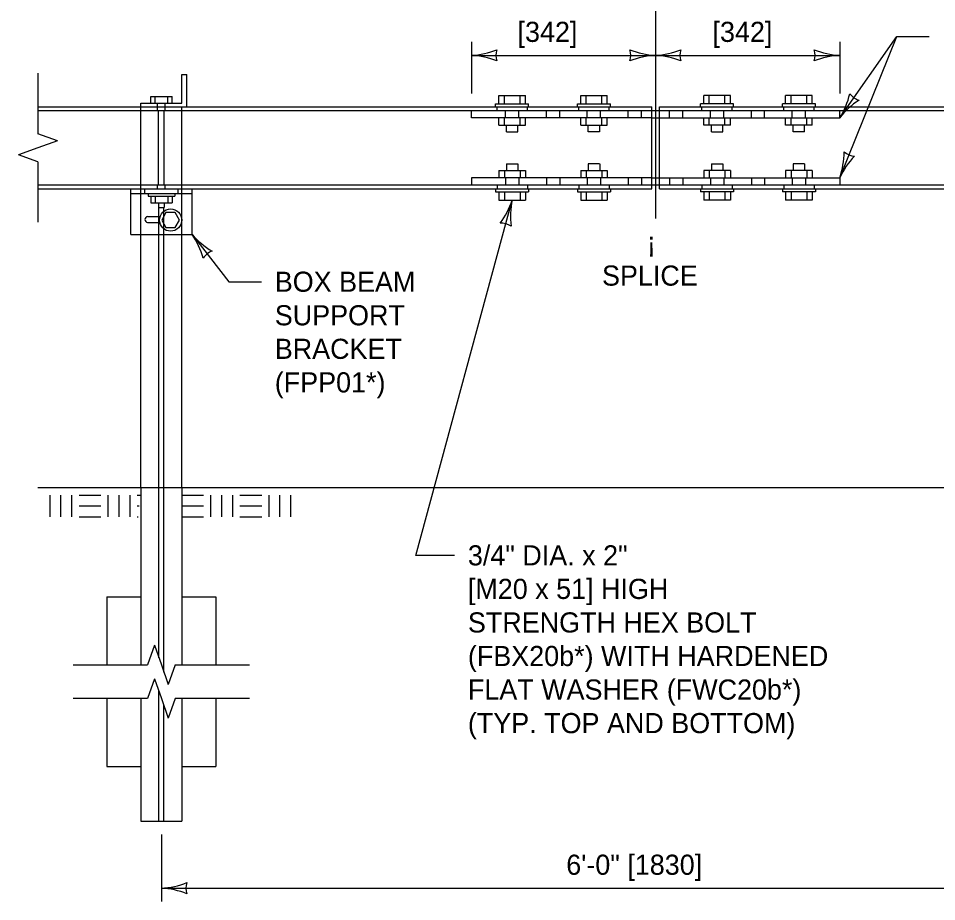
# Model space of a CAD drawing. Extents: x 49991.4 to 50021, y 49987.6 to 50011.4.
# Drawn here: x 50015.21 to 50017.948, y 50004.162 to 50006.795 of the extents above; entities that cross this region are included whole.
import ezdxf

# ---------------------------------------------------------------- set-up
doc = ezdxf.new("R2010")
doc.units = 0
for name, color, linetype in [('Level 1', 7, 'Continuous'), ('Level 2', 7, 'Continuous'), ('Level 3', 7, 'Continuous'), ('Level 4', 7, 'Continuous'), ('Level 5', 7, 'Continuous'), ('Level 6', 7, 'Continuous')]:
    doc.layers.add(name, color=color, linetype=linetype)

msp = doc.modelspace()

# ---------------------------------------------------------------- linework, layer by layer
at = {"layer": 'Level 1'}
for p, q in [((50015.6973, 50006.5419), (50015.6973, 50006.627)), ((50015.6973, 50006.627), (50015.7125, 50006.627)), ((50015.7125, 50006.5309), (50015.7125, 50006.627)), ((50016.6429, 50006.5401), (50016.6429, 50006.5645)), ((50016.6429, 50006.5645), (50016.7218, 50006.5645)), ((50016.659, 50006.5401), (50016.659, 50006.5645)), ((50016.7057, 50006.5401), (50016.7057, 50006.5645)), ((50016.7218, 50006.5401), (50016.7218, 50006.5645)), ((50016.8866, 50006.5401), (50016.8866, 50006.5645)), ((50016.8866, 50006.5645), (50016.9654, 50006.5645)), ((50016.9026, 50006.5401), (50016.9026, 50006.5645)), ((50016.9494, 50006.5401), (50016.9494, 50006.5645)), ((50016.9654, 50006.5401), (50016.9654, 50006.5645)), ((50017.2538, 50006.5401), (50017.2538, 50006.5645)), ((50017.3326, 50006.5645), (50017.2538, 50006.5645)), ((50017.2698, 50006.5401), (50017.2698, 50006.5645)), ((50017.3166, 50006.5401), (50017.3166, 50006.5645)), ((50017.3326, 50006.5401), (50017.3326, 50006.5645)), ((50017.4974, 50006.5401), (50017.4974, 50006.5645)), ((50017.5763, 50006.5645), (50017.4974, 50006.5645)), ((50017.5135, 50006.5401), (50017.5135, 50006.5645)), ((50017.5602, 50006.5401), (50017.5602, 50006.5645)), ((50017.5763, 50006.5401), (50017.5763, 50006.5645)), ((50015.5754, 50006.5309), (50015.5754, 50006.5419)), ((50015.5754, 50006.5419), (50015.6973, 50006.5419)), ((50015.6048, 50006.5419), (50015.6048, 50006.5616)), ((50015.6048, 50006.5616), (50015.6687, 50006.5616)), ((50015.6178, 50006.5419), (50015.6178, 50006.5616)), ((50015.6556, 50006.5419), (50015.6556, 50006.5616)), ((50015.6687, 50006.5419), (50015.6687, 50006.5616)), ((50016.6328, 50006.5401), (50016.7312, 50006.5401)), ((50016.6328, 50006.5309), (50016.6328, 50006.5401)), ((50016.7312, 50006.5309), (50016.7312, 50006.5401)), ((50016.8772, 50006.5401), (50016.9755, 50006.5401)), ((50016.8772, 50006.5309), (50016.8772, 50006.5401)), ((50016.9755, 50006.5309), (50016.9755, 50006.5401)), ((50017.342, 50006.5401), (50017.2437, 50006.5401)), ((50017.2437, 50006.5309), (50017.2437, 50006.5401)), ((50017.342, 50006.5309), (50017.342, 50006.5401)), ((50017.5864, 50006.5401), (50017.488, 50006.5401)), ((50017.488, 50006.5309), (50017.488, 50006.5401)), ((50017.5864, 50006.5309), (50017.5864, 50006.5401)), ((50015.2686, 50006.5309), (50017.0982, 50006.5309)), ((50017.0982, 50006.287), (50017.0982, 50006.5309)), ((50017.0982, 50006.5198), (50017.121, 50006.5198)), ((50017.121, 50006.5309), (50019.3683, 50006.5309)), ((50017.121, 50006.287), (50017.121, 50006.5309)), ((50017.0982, 50006.4982), (50017.121, 50006.4982)), ((50017.0982, 50006.3197), (50017.121, 50006.3197)), ((50017.0982, 50006.2981), (50017.121, 50006.2981)), ((50015.2686, 50006.287), (50017.0982, 50006.287)), ((50015.545, 50006.1508), (50015.545, 50006.287)), ((50015.545, 50006.2724), (50015.7278, 50006.2724)), ((50015.5966, 50006.2724), (50015.5966, 50006.2649)), ((50015.5966, 50006.2649), (50015.6763, 50006.2649)), ((50015.6048, 50006.2649), (50015.6048, 50006.2452)), ((50015.6178, 50006.2649), (50015.6178, 50006.2452)), ((50015.6556, 50006.2649), (50015.6556, 50006.2452)), ((50015.6687, 50006.2649), (50015.6687, 50006.2452)), ((50015.6763, 50006.2724), (50015.6763, 50006.2649)), ((50015.7278, 50006.1508), (50015.7278, 50006.287)), ((50016.6328, 50006.287), (50016.6328, 50006.2777)), ((50016.6328, 50006.2777), (50016.7312, 50006.2777)), ((50016.6429, 50006.2777), (50016.6429, 50006.2533)), ((50016.659, 50006.2777), (50016.659, 50006.2533)), ((50016.7057, 50006.2777), (50016.7057, 50006.2533)), ((50016.7218, 50006.2777), (50016.7218, 50006.2533)), ((50016.7312, 50006.287), (50016.7312, 50006.2777)), ((50016.8772, 50006.287), (50016.8772, 50006.2777)), ((50016.8772, 50006.2777), (50016.9755, 50006.2777)), ((50016.8866, 50006.2777), (50016.8866, 50006.2533)), ((50016.9026, 50006.2777), (50016.9026, 50006.2533)), ((50016.9494, 50006.2777), (50016.9494, 50006.2533)), ((50016.9654, 50006.2777), (50016.9654, 50006.2533)), ((50016.9755, 50006.287), (50016.9755, 50006.2777)), ((50017.121, 50006.287), (50019.3683, 50006.287)), ((50017.2437, 50006.287), (50017.2437, 50006.2777)), ((50017.342, 50006.2777), (50017.2437, 50006.2777)), ((50017.2538, 50006.2777), (50017.2538, 50006.2533)), ((50017.2698, 50006.2777), (50017.2698, 50006.2533)), ((50017.3166, 50006.2777), (50017.3166, 50006.2533)), ((50017.3326, 50006.2777), (50017.3326, 50006.2533)), ((50017.342, 50006.287), (50017.342, 50006.2777)), ((50017.488, 50006.287), (50017.488, 50006.2777)), ((50017.5864, 50006.2777), (50017.488, 50006.2777)), ((50017.4974, 50006.2777), (50017.4974, 50006.2533)), ((50017.5135, 50006.2777), (50017.5135, 50006.2533)), ((50017.5602, 50006.2777), (50017.5602, 50006.2533)), ((50017.5763, 50006.2777), (50017.5763, 50006.2533)), ((50017.5864, 50006.287), (50017.5864, 50006.2777)), ((50015.6048, 50006.2452), (50015.6687, 50006.2452)), ((50016.6429, 50006.2533), (50016.7218, 50006.2533)), ((50016.8866, 50006.2533), (50016.9654, 50006.2533)), ((50017.3326, 50006.2533), (50017.2538, 50006.2533)), ((50017.5763, 50006.2533), (50017.4974, 50006.2533)), ((50015.5954, 50006.2045), (50015.6326, 50006.2045)), ((50015.5954, 50006.1859), (50015.6316, 50006.1859)), ((50015.545, 50006.1508), (50015.7278, 50006.1508)), ((50015.5754, 50005.3957), (50015.5754, 50006.1508)), ((50015.6973, 50005.3957), (50015.6973, 50006.1508)), ((50019.3683, 50005.3957), (50015.2686, 50005.3957)), ((50015.3046, 50005.3091), (50015.3046, 50005.3741)), ((50015.3371, 50005.3091), (50015.3371, 50005.3741)), ((50015.3696, 50005.3091), (50015.3696, 50005.3741)), ((50015.3913, 50005.3741), (50015.4563, 50005.3741)), ((50015.478, 50005.3091), (50015.478, 50005.3741)), ((50015.5105, 50005.3091), (50015.5105, 50005.3741)), ((50015.543, 50005.3091), (50015.543, 50005.3741)), ((50015.6974, 50005.3741), (50015.6974, 50005.3741)), ((50015.6974, 50005.3741), (50015.7623, 50005.3741)), ((50015.7841, 50005.3091), (50015.7841, 50005.3741)), ((50015.8166, 50005.3091), (50015.8166, 50005.3741)), ((50015.849, 50005.3091), (50015.849, 50005.3741)), ((50015.8707, 50005.3741), (50015.9357, 50005.3741)), ((50015.9574, 50005.3091), (50015.9574, 50005.3741)), ((50015.9899, 50005.3091), (50015.9899, 50005.3741)), ((50016.0224, 50005.3091), (50016.0224, 50005.3741)), ((50015.3913, 50005.3416), (50015.4563, 50005.3416)), ((50015.6974, 50005.3416), (50015.7623, 50005.3416)), ((50015.8707, 50005.3416), (50015.9357, 50005.3416)), ((50015.3913, 50005.3091), (50015.4563, 50005.3091)), ((50015.6974, 50005.3091), (50015.7623, 50005.3091)), ((50015.8707, 50005.3091), (50015.9357, 50005.3091))]:
    msp.add_line(p, q, dxfattribs=at)
for points in [[(50015.6279, 50006.2452), (50015.6279, 50006.231)], [(50015.6449, 50006.2452), (50015.6449, 50006.231)], [(50015.6279, 50006.231), (50015.6449, 50006.231)], [(50015.5754, 50005.3957), (50015.5754, 50005.3957)], [(50015.6974, 50005.3957), (50015.6974, 50005.3957)], [(50015.5646, 50005.3741), (50015.5735, 50005.3741)], [(50015.5646, 50005.3416), (50015.5705, 50005.3416)], [(50015.5646, 50005.3091), (50015.5674, 50005.3091)]]:
    msp.add_lwpolyline(points, dxfattribs=at)
msp.add_lwpolyline([(50015.6499, 50006.1713), (50015.678, 50006.1713), (50015.6903, 50006.1936), (50015.678, 50006.2161), (50015.6499, 50006.2161), (50015.6376, 50006.1936)], close=True, dxfattribs=at)
msp.add_circle((50015.664, 50006.1936), 0.0333, dxfattribs=at)
msp.add_arc((50015.5968, 50006.1952), 0.00938, 98.5498, 261.4502, dxfattribs=at)
at = {"layer": 'Level 3'}
for p, q in [((50016.395, 50005.1943), (50016.6823, 50006.2533)), ((50016.5102, 50005.1943), (50016.395, 50005.1943))]:
    msp.add_line(p, q, dxfattribs=at)
for points in [[(50017.6587, 50006.4982), (50017.8285, 50006.7405)], [(50017.6587, 50006.3197), (50017.8285, 50006.7405)], [(50017.8285, 50006.7405), (50017.9257, 50006.7405)], [(50016.5605, 50006.7245), (50016.5605, 50006.5709)], [(50017.6587, 50006.7245), (50017.6587, 50006.5709)], [(50016.5605, 50006.6845), (50017.1096, 50006.6845)], [(50017.1096, 50006.6845), (50017.6587, 50006.6845)], [(50015.7278, 50006.1508), (50015.8373, 50006.0098)], [(50015.8373, 50006.0098), (50015.9345, 50006.0098)], [(50015.6364, 50004.3622), (50015.6364, 50004.1622)], [(50015.6364, 50004.2022), (50018.5614, 50004.2022)]]:
    msp.add_lwpolyline(points, dxfattribs=at)
for centre, radius, start, end in [((50016.549, 50006.9172), 0.233, 272.8273, 292.0772), ((50016.6887, 50006.6845), 0.0548, 162.1388, 197.8612), ((50017.1182, 50006.9066), 0.2223, 247.456, 267.6395), ((50016.9808, 50006.6845), 0.0548, 342.1388, 17.8612), ((50017.0975, 50006.9172), 0.233, 272.8273, 292.0772), ((50017.2372, 50006.6845), 0.0548, 162.1388, 197.8612), ((50017.6678, 50006.9066), 0.2223, 247.456, 267.6395), ((50017.5305, 50006.6845), 0.0548, 342.1388, 17.8612), ((50016.5513, 50006.4624), 0.2223, 67.456, 87.6395), ((50017.1205, 50006.4518), 0.233, 92.8273, 112.0772), ((50017.0998, 50006.4624), 0.2223, 67.456, 87.6395), ((50017.6702, 50006.4518), 0.233, 92.8273, 112.0772), ((50017.4615, 50006.6223), 0.233, 327.8051, 347.055), ((50017.7323, 50006.6032), 0.0548, 217.1167, 252.839), ((50017.8354, 50006.3632), 0.2223, 122.4338, 142.6174), ((50017.4386, 50006.3961), 0.233, 340.8524, 0.1022), ((50017.8613, 50006.2281), 0.2223, 135.4811, 155.6646), ((50017.7067, 50006.4386), 0.0548, 230.1639, 265.8863), ((50016.4704, 50006.3203), 0.2223, 322.2773, 342.4608), ((50016.91, 50006.2035), 0.233, 167.6486, 186.8984), ((50016.6488, 50006.1296), 0.0548, 56.9601, 92.6824), ((50015.5467, 50006.0218), 0.2223, 15.2888, 35.4723), ((50015.9045, 50006.3026), 0.233, 220.6601, 239.9099), ((50015.8064, 50006.0495), 0.0548, 109.9716, 145.6939), ((50015.6249, 50004.4349), 0.233, 272.8273, 292.0772), ((50015.7646, 50004.2022), 0.0548, 162.1388, 197.8612), ((50015.6272, 50003.9801), 0.2223, 67.456, 87.6395)]:
    msp.add_arc(centre, radius, start, end, dxfattribs=at)
at = {"layer": 'Level 4'}
for p, q in [((50015.625, 50006.5198), (50015.625, 50006.5419)), ((50015.6477, 50006.5198), (50015.6477, 50006.5419)), ((50015.2686, 50006.5198), (50017.0982, 50006.5198)), ((50015.5754, 50006.1508), (50015.5754, 50006.5309)), ((50015.6279, 50006.2981), (50015.6279, 50006.5198)), ((50015.6449, 50006.2981), (50015.6449, 50006.5198)), ((50015.6973, 50006.1508), (50015.6973, 50006.5309)), ((50016.5605, 50006.4982), (50016.5605, 50006.5198)), ((50016.6626, 50006.4982), (50016.6626, 50006.5198)), ((50016.7022, 50006.4982), (50016.7022, 50006.5198)), ((50016.7844, 50006.4982), (50016.7844, 50006.5198)), ((50016.824, 50006.4982), (50016.824, 50006.5198)), ((50016.9062, 50006.4982), (50016.9062, 50006.5198)), ((50016.9458, 50006.4982), (50016.9458, 50006.5198)), ((50017.028, 50006.4982), (50017.028, 50006.5198)), ((50017.0676, 50006.4982), (50017.0676, 50006.5198)), ((50017.121, 50006.5198), (50019.3683, 50006.5198)), ((50017.1516, 50006.4982), (50017.1516, 50006.5198)), ((50017.1912, 50006.4982), (50017.1912, 50006.5198)), ((50017.2734, 50006.4982), (50017.2734, 50006.5198)), ((50017.313, 50006.4982), (50017.313, 50006.5198)), ((50017.3952, 50006.4982), (50017.3952, 50006.5198)), ((50017.4348, 50006.4982), (50017.4348, 50006.5198)), ((50017.517, 50006.4982), (50017.517, 50006.5198)), ((50017.5566, 50006.4982), (50017.5566, 50006.5198)), ((50017.6587, 50006.4982), (50017.6587, 50006.5198)), ((50017.0982, 50006.4982), (50016.5605, 50006.4982)), ((50016.6429, 50006.4768), (50016.6429, 50006.4982)), ((50016.659, 50006.4768), (50016.659, 50006.4982)), ((50016.7057, 50006.4768), (50016.7057, 50006.4982)), ((50016.7218, 50006.4768), (50016.7218, 50006.4982)), ((50016.8866, 50006.4768), (50016.8866, 50006.4982)), ((50016.9026, 50006.4768), (50016.9026, 50006.4982)), ((50016.9494, 50006.4768), (50016.9494, 50006.4982)), ((50016.9654, 50006.4768), (50016.9654, 50006.4982)), ((50017.121, 50006.4982), (50017.6587, 50006.4982)), ((50017.2538, 50006.4768), (50017.2538, 50006.4982)), ((50017.2698, 50006.4768), (50017.2698, 50006.4982)), ((50017.3166, 50006.4768), (50017.3166, 50006.4982)), ((50017.3326, 50006.4768), (50017.3326, 50006.4982)), ((50017.4974, 50006.4768), (50017.4974, 50006.4982)), ((50017.5135, 50006.4768), (50017.5135, 50006.4982)), ((50017.5602, 50006.4768), (50017.5602, 50006.4982)), ((50017.5763, 50006.4768), (50017.5763, 50006.4982)), ((50016.6429, 50006.4768), (50016.7218, 50006.4768)), ((50016.6654, 50006.4567), (50016.6654, 50006.4768)), ((50016.6654, 50006.4567), (50016.6994, 50006.4567)), ((50016.6994, 50006.4567), (50016.6994, 50006.4768)), ((50016.8866, 50006.4768), (50016.9654, 50006.4768)), ((50016.909, 50006.4567), (50016.909, 50006.4768)), ((50016.9429, 50006.4567), (50016.909, 50006.4567)), ((50016.943, 50006.4567), (50016.943, 50006.4768)), ((50017.3326, 50006.4768), (50017.2538, 50006.4768)), ((50017.2762, 50006.4567), (50017.2762, 50006.4768)), ((50017.2763, 50006.4567), (50017.3102, 50006.4567)), ((50017.3102, 50006.4567), (50017.3102, 50006.4768)), ((50017.5763, 50006.4768), (50017.4974, 50006.4768)), ((50017.5198, 50006.4567), (50017.5198, 50006.4768)), ((50017.5538, 50006.4567), (50017.5198, 50006.4567)), ((50017.5538, 50006.4567), (50017.5538, 50006.4768)), ((50016.6654, 50006.3612), (50016.6654, 50006.3411)), ((50016.6654, 50006.3612), (50016.6994, 50006.3612)), ((50016.6994, 50006.3612), (50016.6994, 50006.3411)), ((50016.909, 50006.3612), (50016.909, 50006.3411)), ((50016.9429, 50006.3612), (50016.909, 50006.3612)), ((50016.943, 50006.3612), (50016.943, 50006.3411)), ((50017.2762, 50006.3612), (50017.2762, 50006.3411)), ((50017.2763, 50006.3612), (50017.3102, 50006.3612)), ((50017.3102, 50006.3612), (50017.3102, 50006.3411)), ((50017.5198, 50006.3612), (50017.5198, 50006.3411)), ((50017.5538, 50006.3612), (50017.5198, 50006.3612)), ((50017.5538, 50006.3612), (50017.5538, 50006.3411)), ((50017.0982, 50006.3197), (50016.5605, 50006.3197)), ((50016.5605, 50006.3197), (50016.5605, 50006.2981)), ((50016.6429, 50006.3411), (50016.6429, 50006.3197)), ((50016.6429, 50006.3411), (50016.7218, 50006.3411)), ((50016.659, 50006.3411), (50016.659, 50006.3197)), ((50016.6626, 50006.3197), (50016.6626, 50006.2981)), ((50016.7022, 50006.3197), (50016.7022, 50006.2981)), ((50016.7057, 50006.3411), (50016.7057, 50006.3197)), ((50016.7218, 50006.3411), (50016.7218, 50006.3197)), ((50016.7844, 50006.3197), (50016.7844, 50006.2981)), ((50016.824, 50006.3197), (50016.824, 50006.2981)), ((50016.8866, 50006.3411), (50016.8866, 50006.3197)), ((50016.8866, 50006.3411), (50016.9654, 50006.3411)), ((50016.9026, 50006.3411), (50016.9026, 50006.3197)), ((50016.9062, 50006.3197), (50016.9062, 50006.2981)), ((50016.9458, 50006.3197), (50016.9458, 50006.2981)), ((50016.9494, 50006.3411), (50016.9494, 50006.3197)), ((50016.9654, 50006.3411), (50016.9654, 50006.3197)), ((50017.028, 50006.3197), (50017.028, 50006.2981)), ((50017.0676, 50006.3197), (50017.0676, 50006.2981)), ((50017.121, 50006.3197), (50017.6587, 50006.3197)), ((50017.1516, 50006.3197), (50017.1516, 50006.2981)), ((50017.1912, 50006.3197), (50017.1912, 50006.2981)), ((50017.2538, 50006.3411), (50017.2538, 50006.3197)), ((50017.3326, 50006.3411), (50017.2538, 50006.3411)), ((50017.2698, 50006.3411), (50017.2698, 50006.3197)), ((50017.2734, 50006.3197), (50017.2734, 50006.2981)), ((50017.313, 50006.3197), (50017.313, 50006.2981)), ((50017.3166, 50006.3411), (50017.3166, 50006.3197)), ((50017.3326, 50006.3411), (50017.3326, 50006.3197)), ((50017.3952, 50006.3197), (50017.3952, 50006.2981)), ((50017.4348, 50006.3197), (50017.4348, 50006.2981)), ((50017.4974, 50006.3411), (50017.4974, 50006.3197)), ((50017.5763, 50006.3411), (50017.4974, 50006.3411)), ((50017.5135, 50006.3411), (50017.5135, 50006.3197)), ((50017.517, 50006.3197), (50017.517, 50006.2981)), ((50017.5566, 50006.3197), (50017.5566, 50006.2981)), ((50017.5602, 50006.3411), (50017.5602, 50006.3197)), ((50017.5763, 50006.3411), (50017.5763, 50006.3197)), ((50017.6587, 50006.3197), (50017.6587, 50006.2981)), ((50015.2686, 50006.2981), (50017.0982, 50006.2981)), ((50015.625, 50006.287), (50015.625, 50006.2981)), ((50015.6477, 50006.287), (50015.6477, 50006.2981)), ((50017.121, 50006.2981), (50019.3683, 50006.2981)), ((50015.5874, 50006.2724), (50015.5874, 50006.287)), ((50015.6861, 50006.2724), (50015.6861, 50006.287)), ((50015.6288, 50004.889), (50015.6288, 50006.231)), ((50015.644, 50004.8461), (50015.644, 50006.231)), ((50015.5754, 50005.3957), (50015.5754, 50004.8676)), ((50015.6974, 50005.3957), (50015.6974, 50004.8676)), ((50015.4739, 50005.0708), (50015.5754, 50005.0708)), ((50015.4739, 50005.0708), (50015.4739, 50004.8676)), ((50015.6974, 50005.0708), (50015.7989, 50005.0708)), ((50015.7989, 50005.0708), (50015.7989, 50004.8676)), ((50015.6288, 50004.4022), (50015.6288, 50004.7893)), ((50015.4739, 50004.7678), (50015.4739, 50004.5647)), ((50015.5754, 50004.7678), (50015.5754, 50004.4022)), ((50015.6974, 50004.7678), (50015.6974, 50004.4022)), ((50015.7989, 50004.7678), (50015.7989, 50004.5647)), ((50015.644, 50004.4022), (50015.644, 50004.7464)), ((50015.4739, 50004.5647), (50015.5754, 50004.5647)), ((50015.6974, 50004.5647), (50015.7989, 50004.5647)), ((50015.5754, 50004.4022), (50015.6974, 50004.4022))]:
    msp.add_line(p, q, dxfattribs=at)
for points in [[(50016.6372, 50006.5198), (50016.6372, 50006.5309)], [(50016.7276, 50006.5198), (50016.7276, 50006.5309)], [(50016.8809, 50006.5198), (50016.8809, 50006.5309)], [(50016.9713, 50006.5198), (50016.9713, 50006.5309)], [(50017.2479, 50006.5198), (50017.2479, 50006.5309)], [(50017.3383, 50006.5198), (50017.3383, 50006.5309)], [(50017.4916, 50006.5198), (50017.4916, 50006.5309)], [(50017.582, 50006.5198), (50017.582, 50006.5309)], [(50016.6372, 50006.2981), (50016.6372, 50006.287)], [(50016.7276, 50006.2981), (50016.7276, 50006.287)], [(50016.8809, 50006.2981), (50016.8809, 50006.287)], [(50016.9713, 50006.2981), (50016.9713, 50006.287)], [(50017.2479, 50006.2981), (50017.2479, 50006.287)], [(50017.3383, 50006.2981), (50017.3383, 50006.287)], [(50017.4916, 50006.2981), (50017.4916, 50006.287)], [(50017.582, 50006.2981), (50017.582, 50006.287)]]:
    msp.add_lwpolyline(points, dxfattribs=at)
at = {"layer": 'Level 5'}
msp.add_lwpolyline([(50017.109, 50007.7118), (50017.109, 50006.1981)], dxfattribs=at)
at = {"layer": 'Level 6'}
for p, q in [((50015.2686, 50006.6309), (50015.2686, 50006.4501)), ((50015.327, 50006.4293), (50015.2686, 50006.4501)), ((50015.327, 50006.4293), (50015.2686, 50006.4086)), ((50015.2686, 50006.4086), (50015.2101, 50006.3879)), ((50015.2686, 50006.3672), (50015.2101, 50006.3879)), ((50015.2686, 50006.3672), (50015.2686, 50006.187)), ((50015.6157, 50004.9261), (50015.595, 50004.8676)), ((50015.6157, 50004.9261), (50015.6364, 50004.8676)), ((50015.3739, 50004.8676), (50015.595, 50004.8676)), ((50015.6364, 50004.8676), (50015.6571, 50004.8091)), ((50015.6778, 50004.8676), (50015.6571, 50004.8091)), ((50015.6778, 50004.8676), (50015.8989, 50004.8676)), ((50015.6157, 50004.8263), (50015.595, 50004.7678)), ((50015.6157, 50004.8263), (50015.6364, 50004.7678)), ((50015.595, 50004.7678), (50015.3739, 50004.7678)), ((50015.6364, 50004.7678), (50015.6571, 50004.7093)), ((50015.6778, 50004.7678), (50015.6571, 50004.7093)), ((50015.8989, 50004.7678), (50015.6778, 50004.7678))]:
    msp.add_line(p, q, dxfattribs=at)

# ---------------------------------------------------------------- texts
at = {"layer": 'Level 2'}
for s, p in [('[342]', (50016.6982, 50006.7245)), ('[342]', (50017.2794, 50006.7245)), ('¡', (50017.0839, 50006.0981)), ('SPLICE', (50016.95, 50005.9981)), ('BOX BEAM', (50015.9745, 50005.9798)), ('SUPPORT', (50015.9745, 50005.8798)), ('BRACKET', (50015.9745, 50005.7798)), ('(FPP01*)', (50015.9745, 50005.6798)), ('3/4" DIA. x 2" ', (50016.5502, 50005.1643)), ('[M20 x 51] HIGH', (50016.5502, 50005.0643)), ('STRENGTH HEX BOLT', (50016.5502, 50004.9643)), ('(FBX20b*) WITH HARDENED', (50016.5502, 50004.8643)), ('FLAT WASHER (FWC20b*)', (50016.5502, 50004.7643)), ('(TYP. TOP AND BOTTOM)', (50016.5502, 50004.6643)), ('6\'-0" [1830]', (50016.8434, 50004.2422))]:
    msp.add_text(s, height=0.06, dxfattribs=at).set_placement(p)

doc.saveas('drawing.dxf')
